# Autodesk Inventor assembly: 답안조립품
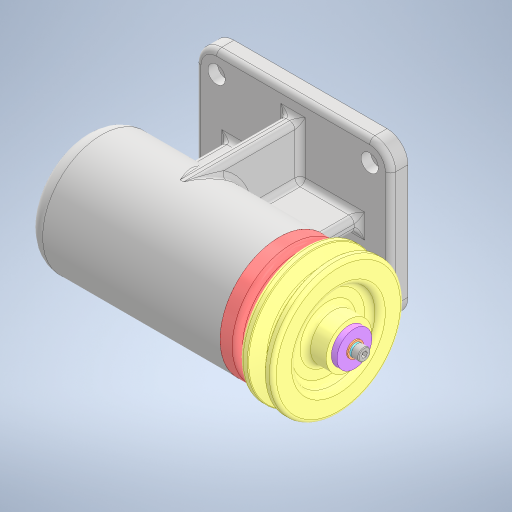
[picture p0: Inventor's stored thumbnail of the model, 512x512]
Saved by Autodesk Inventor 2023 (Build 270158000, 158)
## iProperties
Created: 2026-08
Part Number: 답안조립품
Document SubType Name: Assembly
Designer: home
Author: home
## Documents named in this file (14)
- C:\Users\kimgi\Desktop\760803V1006\답안조립품.iam
- C:\Users\kimgi\Desktop\760803V1006\본체.ipt
- C:\Users\kimgi\Desktop\760803V1006\커버.ipt
- C:\Users\kimgi\Desktop\760803V1006\축.ipt
- C:\Users\kimgi\Desktop\760803V1006\V 벨트 풀리.ipt
- C:\Users\kimgi\Desktop\760803V1006\오일 실 20 32 5.ipt
- C:\Users\kimgi\Desktop\760803V1006\평행 키 5x5x16.ipt
- C:\Users\kimgi\Desktop\760803V1006\엔드 캡.ipt
- C:\Users\kimgi\Desktop\760803V1006\스프링 와셔 M4.ipt
- C:\Users\kimgi\Desktop\760803V1006\평 와셔 M4.ipt
- C:\Users\kimgi\Desktop\760803V1006\6각 구멍붙이 볼트 M4x12.ipt
- C:\Users\kimgi\Desktop\760803V1006\깊은 홈 볼 베어링 6004.ipt
- C:\Users\kimgi\Desktop\760803V1006\어댑터 슬리브.ipt
- C:\Users\kimgi\Desktop\760803V1006\스러스트 볼 베어링 51202.ipt
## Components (7 placed, 2 different names)
1. V 벨트 풀리:1 — 각도:4
2. 6각 구멍붙이 볼트 M4x12:1 — 각도:5
3. 6각 구멍붙이 볼트 M4x12:6 — 각도:7
4. 6각 구멍붙이 볼트 M4x12:2 — 각도:6
5. 6각 구멍붙이 볼트 M4x12:3
6. 6각 구멍붙이 볼트 M4x12:4
7. 6각 구멍붙이 볼트 M4x12:5
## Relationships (4: Angle 4)
- 각도:4 [Angle]: V 벨트 풀리:1
- 각도:5 [Angle]: 6각 구멍붙이 볼트 M4x12:1
- 각도:6 [Angle]: 6각 구멍붙이 볼트 M4x12:2
- 각도:7 [Angle]: 6각 구멍붙이 볼트 M4x12:6
